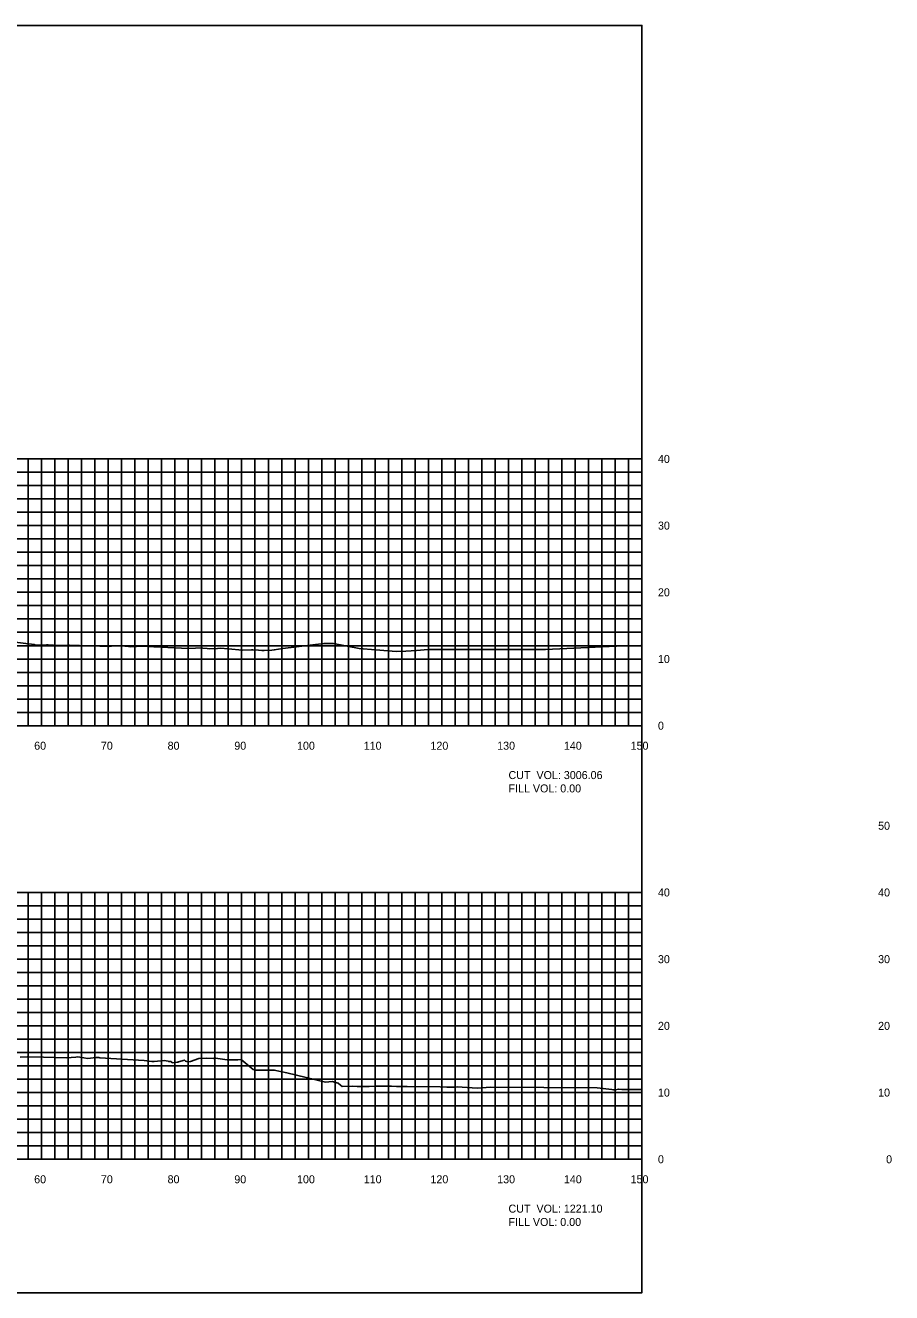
# Model space of a CAD drawing. Extents: x 1800976 to 1805104, y 250057 to 250580.
# Drawn here: x 1803708.6 to 1803838.4, y 250079.4 to 250269.4 of the extents above; entities that cross this region are included whole.
import ezdxf

# ---------------------------------------------------------------- set-up
doc = ezdxf.new("R2010")
doc.units = 0
for name, color, linetype in [('10', 7, 'Continuous'), ('31', 7, 'Continuous'), ('60', 7, 'Continuous'), ('ANNO-TXT', 7, 'Continuous'), ('Level 62', 7, 'Continuous'), ('M-ROADS', 7, 'Continuous')]:
    doc.layers.add(name, color=color, linetype=linetype)

msp = doc.modelspace()

# ---------------------------------------------------------------- linework, layer by layer
msp.add_lwpolyline([(1803501, 250079.43), (1803801, 250079.43), (1803801, 250269.43), (1803501, 250269.43)], close=True)
at = {"layer": '60'}
for p, q in [((1803801, 250164.43), (1803801, 250204.43)), ((1803801.06, 250204.43), (1803801, 250204.43)), ((1803801.06, 250194.43), (1803801, 250194.43)), ((1803801.06, 250184.43), (1803801, 250184.43)), ((1803801.06, 250174.43), (1803801, 250174.43)), ((1803501, 250164.43), (1803801, 250164.43)), ((1803711, 250164.37), (1803711, 250164.43)), ((1803721, 250164.37), (1803721, 250164.43)), ((1803731, 250164.37), (1803731, 250164.43)), ((1803741, 250164.37), (1803741, 250164.43)), ((1803751, 250164.37), (1803751, 250164.43)), ((1803761, 250164.37), (1803761, 250164.43)), ((1803771, 250164.37), (1803771, 250164.43)), ((1803781, 250164.37), (1803781, 250164.43)), ((1803791, 250164.37), (1803791, 250164.43)), ((1803801, 250164.37), (1803801, 250164.43)), ((1803801.06, 250164.43), (1803801, 250164.43)), ((1803801, 250099.43), (1803801, 250139.43)), ((1803801.06, 250139.43), (1803801, 250139.43)), ((1803801.06, 250129.43), (1803801, 250129.43)), ((1803801.06, 250119.43), (1803801, 250119.43)), ((1803801.06, 250109.43), (1803801, 250109.43)), ((1803501, 250099.43), (1803801, 250099.43)), ((1803711, 250099.37), (1803711, 250099.43)), ((1803721, 250099.37), (1803721, 250099.43)), ((1803731, 250099.37), (1803731, 250099.43)), ((1803741, 250099.37), (1803741, 250099.43)), ((1803751, 250099.37), (1803751, 250099.43)), ((1803761, 250099.37), (1803761, 250099.43)), ((1803771, 250099.37), (1803771, 250099.43)), ((1803781, 250099.37), (1803781, 250099.43)), ((1803791, 250099.37), (1803791, 250099.43)), ((1803801, 250099.37), (1803801, 250099.43)), ((1803801.06, 250099.43), (1803801, 250099.43))]:
    msp.add_line(p, q, dxfattribs=at)
at = {"layer": 'Level 62'}
for p, q in [((1803501, 250204.43), (1803801, 250204.43)), ((1803709, 250164.43), (1803709, 250204.43)), ((1803711, 250164.43), (1803711, 250204.43)), ((1803713, 250164.43), (1803713, 250204.43)), ((1803715, 250164.43), (1803715, 250204.43)), ((1803717, 250164.43), (1803717, 250204.43)), ((1803719, 250164.43), (1803719, 250204.43)), ((1803721, 250164.43), (1803721, 250204.43)), ((1803723, 250164.43), (1803723, 250204.43)), ((1803725, 250164.43), (1803725, 250204.43)), ((1803727, 250164.43), (1803727, 250204.43)), ((1803729, 250164.43), (1803729, 250204.43)), ((1803731, 250164.43), (1803731, 250204.43)), ((1803733, 250164.43), (1803733, 250204.43)), ((1803735, 250164.43), (1803735, 250204.43)), ((1803737, 250164.43), (1803737, 250204.43)), ((1803739, 250164.43), (1803739, 250204.43)), ((1803741, 250164.43), (1803741, 250204.43)), ((1803743, 250164.43), (1803743, 250204.43)), ((1803745, 250164.43), (1803745, 250204.43)), ((1803747, 250164.43), (1803747, 250204.43)), ((1803749, 250164.43), (1803749, 250204.43)), ((1803751, 250164.43), (1803751, 250204.43)), ((1803753, 250164.43), (1803753, 250204.43)), ((1803755, 250164.43), (1803755, 250204.43)), ((1803757, 250164.43), (1803757, 250204.43)), ((1803759, 250164.43), (1803759, 250204.43)), ((1803761, 250164.43), (1803761, 250204.43)), ((1803763, 250164.43), (1803763, 250204.43)), ((1803765, 250164.43), (1803765, 250204.43)), ((1803767, 250164.43), (1803767, 250204.43)), ((1803769, 250164.43), (1803769, 250204.43)), ((1803771, 250164.43), (1803771, 250204.43)), ((1803773, 250164.43), (1803773, 250204.43)), ((1803775, 250164.43), (1803775, 250204.43)), ((1803777, 250164.43), (1803777, 250204.43)), ((1803779, 250164.43), (1803779, 250204.43)), ((1803781, 250164.43), (1803781, 250204.43)), ((1803783, 250164.43), (1803783, 250204.43)), ((1803785, 250164.43), (1803785, 250204.43)), ((1803787, 250164.43), (1803787, 250204.43)), ((1803789, 250164.43), (1803789, 250204.43)), ((1803791, 250164.43), (1803791, 250204.43)), ((1803793, 250164.43), (1803793, 250204.43)), ((1803795, 250164.43), (1803795, 250204.43)), ((1803797, 250164.43), (1803797, 250204.43)), ((1803799, 250164.43), (1803799, 250204.43)), ((1803801, 250164.43), (1803801, 250204.43)), ((1803501, 250202.43), (1803801, 250202.43)), ((1803501, 250200.43), (1803801, 250200.43)), ((1803501, 250198.43), (1803801, 250198.43)), ((1803501, 250196.43), (1803801, 250196.43)), ((1803501, 250194.43), (1803801, 250194.43)), ((1803501, 250192.43), (1803801, 250192.43)), ((1803501, 250190.43), (1803801, 250190.43)), ((1803501, 250188.43), (1803801, 250188.43)), ((1803501, 250186.43), (1803801, 250186.43)), ((1803501, 250184.43), (1803801, 250184.43)), ((1803501, 250182.43), (1803801, 250182.43)), ((1803501, 250180.43), (1803801, 250180.43)), ((1803501, 250178.43), (1803801, 250178.43)), ((1803501, 250176.43), (1803801, 250176.43)), ((1803501, 250174.43), (1803801, 250174.43)), ((1803501, 250172.43), (1803801, 250172.43)), ((1803501, 250170.43), (1803801, 250170.43)), ((1803501, 250168.43), (1803801, 250168.43)), ((1803501, 250166.43), (1803801, 250166.43)), ((1803501, 250164.43), (1803801, 250164.43)), ((1803501, 250139.43), (1803801, 250139.43)), ((1803709, 250099.43), (1803709, 250139.43)), ((1803711, 250099.43), (1803711, 250139.43)), ((1803713, 250099.43), (1803713, 250139.43)), ((1803715, 250099.43), (1803715, 250139.43)), ((1803717, 250099.43), (1803717, 250139.43)), ((1803719, 250099.43), (1803719, 250139.43)), ((1803721, 250099.43), (1803721, 250139.43)), ((1803723, 250099.43), (1803723, 250139.43)), ((1803725, 250099.43), (1803725, 250139.43)), ((1803727, 250099.43), (1803727, 250139.43)), ((1803729, 250099.43), (1803729, 250139.43)), ((1803731, 250099.43), (1803731, 250139.43)), ((1803733, 250099.43), (1803733, 250139.43)), ((1803735, 250099.43), (1803735, 250139.43)), ((1803737, 250099.43), (1803737, 250139.43)), ((1803739, 250099.43), (1803739, 250139.43)), ((1803741, 250099.43), (1803741, 250139.43)), ((1803743, 250099.43), (1803743, 250139.43)), ((1803745, 250099.43), (1803745, 250139.43)), ((1803747, 250099.43), (1803747, 250139.43)), ((1803749, 250099.43), (1803749, 250139.43)), ((1803751, 250099.43), (1803751, 250139.43)), ((1803753, 250099.43), (1803753, 250139.43)), ((1803755, 250099.43), (1803755, 250139.43)), ((1803757, 250099.43), (1803757, 250139.43)), ((1803759, 250099.43), (1803759, 250139.43)), ((1803761, 250099.43), (1803761, 250139.43)), ((1803763, 250099.43), (1803763, 250139.43)), ((1803765, 250099.43), (1803765, 250139.43)), ((1803767, 250099.43), (1803767, 250139.43)), ((1803769, 250099.43), (1803769, 250139.43)), ((1803771, 250099.43), (1803771, 250139.43)), ((1803773, 250099.43), (1803773, 250139.43)), ((1803775, 250099.43), (1803775, 250139.43)), ((1803777, 250099.43), (1803777, 250139.43)), ((1803779, 250099.43), (1803779, 250139.43)), ((1803781, 250099.43), (1803781, 250139.43)), ((1803783, 250099.43), (1803783, 250139.43)), ((1803785, 250099.43), (1803785, 250139.43)), ((1803787, 250099.43), (1803787, 250139.43)), ((1803789, 250099.43), (1803789, 250139.43)), ((1803791, 250099.43), (1803791, 250139.43)), ((1803793, 250099.43), (1803793, 250139.43)), ((1803795, 250099.43), (1803795, 250139.43)), ((1803797, 250099.43), (1803797, 250139.43)), ((1803799, 250099.43), (1803799, 250139.43)), ((1803801, 250099.43), (1803801, 250139.43)), ((1803501, 250137.43), (1803801, 250137.43)), ((1803501, 250135.43), (1803801, 250135.43)), ((1803501, 250133.43), (1803801, 250133.43)), ((1803501, 250131.43), (1803801, 250131.43)), ((1803501, 250129.43), (1803801, 250129.43)), ((1803501, 250127.43), (1803801, 250127.43)), ((1803501, 250125.43), (1803801, 250125.43)), ((1803501, 250123.43), (1803801, 250123.43)), ((1803501, 250121.43), (1803801, 250121.43)), ((1803501, 250119.43), (1803801, 250119.43)), ((1803501, 250117.43), (1803801, 250117.43)), ((1803501, 250115.43), (1803801, 250115.43)), ((1803501, 250113.43), (1803801, 250113.43)), ((1803501, 250111.43), (1803801, 250111.43)), ((1803501, 250109.43), (1803801, 250109.43)), ((1803501, 250107.43), (1803801, 250107.43)), ((1803501, 250105.43), (1803801, 250105.43)), ((1803501, 250103.43), (1803801, 250103.43)), ((1803501, 250101.43), (1803801, 250101.43)), ((1803501, 250099.43), (1803801, 250099.43))]:
    msp.add_line(p, q, dxfattribs=at)
at = {"layer": 'M-ROADS'}
for points in [[(1803705.82, 250177.11), (1803709.91, 250176.63), (1803710.16, 250176.49), (1803711.73, 250176.55), (1803711.87, 250176.56), (1803711.91, 250176.56), (1803711.98, 250176.55), (1803712.81, 250176.49), (1803713.27, 250176.45), (1803714.93, 250176.52), (1803714.97, 250176.52), (1803715.02, 250176.52), (1803715.19, 250176.52), (1803721.23, 250176.33), (1803721.8, 250176.39), (1803722.18, 250176.42), (1803722.92, 250176.4), (1803723.51, 250176.36), (1803723.67, 250176.35), (1803724.33, 250176.28), (1803725.24, 250176.32), (1803726.04, 250176.36), (1803727.82, 250176.28), (1803733.03, 250176.02), (1803734.09, 250176.06), (1803734.92, 250176.09), (1803735.2, 250176.07), (1803735.82, 250176), (1803736.14, 250175.97), (1803737.37, 250176.02), (1803737.85, 250176.05), (1803738.96, 250175.95), (1803741.14, 250175.76), (1803742.48, 250175.82), (1803742.65, 250175.83), (1803742.7, 250175.83), (1803743.51, 250175.77), (1803744.02, 250175.73), (1803744.37, 250175.7), (1803745.51, 250175.77), (1803745.88, 250175.79), (1803747.18, 250176.01), (1803753.3, 250176.77), (1803754.79, 250176.74), (1803758.61, 250176.03), (1803761.08, 250175.8), (1803764.22, 250175.56), (1803765.62, 250175.62), (1803767.22, 250175.7), (1803768.95, 250175.88), (1803777.66, 250175.87), (1803779.59, 250175.86), (1803782.36, 250175.85), (1803783.91, 250175.85), (1803786.38, 250175.85), (1803786.53, 250175.86), (1803798.22, 250176.42), (1803800.85, 250176.44), (1803801, 250176.44)], [(1803707.8, 250114.73), (1803708.85, 250114.8), (1803711.29, 250114.74), (1803714.76, 250114.65), (1803716.16, 250114.75), (1803716.46, 250114.77), (1803716.72, 250114.74), (1803717.33, 250114.65), (1803717.87, 250114.55), (1803719.21, 250114.67), (1803719.57, 250114.67), (1803719.76, 250114.63), (1803726.4, 250114.24), (1803727.52, 250114.11), (1803727.89, 250114.11), (1803728.87, 250114.18), (1803729.39, 250114.23), (1803729.97, 250114.16), (1803730.04, 250114.11), (1803730.42, 250114.11), (1803730.6, 250113.91), (1803731.33, 250113.99), (1803731.44, 250114), (1803731.46, 250114), (1803731.51, 250114.04), (1803732.44, 250114.31), (1803732.57, 250114.12), (1803732.93, 250114.04), (1803733.31, 250114.1), (1803734.59, 250114.55), (1803735.74, 250114.58), (1803736.75, 250114.54), (1803736.96, 250114.62), (1803737.08, 250114.61), (1803738.84, 250114.33), (1803740.43, 250114.33), (1803740.92, 250114.38), (1803742.73, 250112.89), (1803742.91, 250112.84), (1803743.04, 250112.79), (1803745.89, 250112.8), (1803747.77, 250112.37), (1803753.56, 250111), (1803754.57, 250111.07), (1803755.49, 250110.85), (1803755.83, 250110.53), (1803756.06, 250110.36), (1803757.6, 250110.37), (1803758.33, 250110.36), (1803759.22, 250110.34), (1803759.49, 250110.34), (1803759.66, 250110.33), (1803759.75, 250110.34), (1803760.12, 250110.33), (1803760.92, 250110.39), (1803760.96, 250110.39), (1803761, 250110.39), (1803761.09, 250110.4), (1803761.19, 250110.39), (1803761.5, 250110.37), (1803763.48, 250110.37), (1803764.2, 250110.33), (1803765.83, 250110.33), (1803770.74, 250110.28), (1803771.76, 250110.25), (1803772.94, 250110.26), (1803773.04, 250110.26), (1803773.11, 250110.26), (1803773.28, 250110.28), (1803776.31, 250110.11), (1803778.29, 250110.26), (1803794.29, 250110.14), (1803796.49, 250109.87), (1803796.73, 250109.85), (1803796.98, 250109.85), (1803797.53, 250109.96), (1803797.54, 250109.94), (1803798, 250109.9), (1803798.25, 250109.88), (1803800.45, 250109.91), (1803801, 250109.89)]]:
    msp.add_lwpolyline(points, dxfattribs=at)

# ---------------------------------------------------------------- texts
at = {"layer": '10'}
for s, p in [('60', (1803709.9, 250160.83)), ('70', (1803719.9, 250160.83)), ('80', (1803729.9, 250160.83)), ('90', (1803739.9, 250160.83)), ('100', (1803749.3, 250160.83)), ('110', (1803759.3, 250160.83)), ('120', (1803769.3, 250160.83)), ('130', (1803779.3, 250160.83)), ('140', (1803789.3, 250160.83)), ('150', (1803799.3, 250160.83)), ('60', (1803709.9, 250095.83)), ('70', (1803719.9, 250095.83)), ('80', (1803729.9, 250095.83)), ('90', (1803739.9, 250095.83)), ('100', (1803749.3, 250095.83)), ('110', (1803759.3, 250095.83)), ('120', (1803769.3, 250095.83)), ('130', (1803779.3, 250095.83)), ('140', (1803789.3, 250095.83)), ('150', (1803799.3, 250095.83))]:
    msp.add_text(s, height=1.2, dxfattribs=at).set_placement(p)
at = {"layer": '31'}
for s, p in [('40', (1803803.4, 250203.83)), ('30', (1803803.4, 250193.83)), ('20', (1803803.4, 250183.83)), ('10', (1803803.4, 250173.83)), ('0', (1803803.4, 250163.83)), ('50', (1803836.4, 250148.83)), ('40', (1803803.4, 250138.83)), ('40', (1803836.4, 250138.83)), ('30', (1803803.4, 250128.83)), ('30', (1803836.4, 250128.83)), ('20', (1803803.4, 250118.83)), ('20', (1803836.4, 250118.83)), ('10', (1803803.4, 250108.83)), ('10', (1803836.4, 250108.83)), ('0', (1803803.4, 250098.83)), ('0', (1803837.6, 250098.83))]:
    msp.add_text(s, height=1.2, dxfattribs=at).set_placement(p)
at = {"layer": 'ANNO-TXT'}
for s, p in [('CUT  VOL: 3006.06', (1803781, 250156.43)), ('FILL VOL: 0.00', (1803781, 250154.43)), ('CUT  VOL: 1221.10', (1803781, 250091.43)), ('FILL VOL: 0.00', (1803781, 250089.43))]:
    msp.add_text(s, height=1.2, dxfattribs=at).set_placement(p)

doc.saveas('drawing.dxf')
